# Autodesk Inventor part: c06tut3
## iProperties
Shininess: 77.0
Length Units: 11269
Angle Units: 11279
Time Units: 11290
Mass Units: 11283
Length Display Precision: 3
Angle Display Precision: 2
Created: 2001-12
Part Number: c06tut3
Document SubType Name: Modeling
Designer: Renu Muthoo
Density: 1 g/cm^3
Density: 0.0
Volumn: 0.0
Area: 0.0
PropertySet Name: Model Information
Control State: 0
Master: False
Checked Out: False
Author: Renu Muthoo
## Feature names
1. Extrusion1
2. Extrusion2
3. Extrusion3
4. Hole1
5. Hole2
6. Circular Pattern1
7. Extrusion4
8. Circular Pattern2
9. Mirror1
